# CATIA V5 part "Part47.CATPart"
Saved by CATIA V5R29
Part number: pan head cross recess screw_iso_ISO 7045 - M4 x 6 - Z - 6N
Revision: ANY
Definition: UNKNOWN
Nomenclature: pan head cross recess screw_iso_ISO 7045 - M4 x 6 - Z - 6N
Source: Unknown
Bounding box of the stored display mesh (mm): x 0.079 to 9.1, y -3.991 to 3.991, z -4 to 4
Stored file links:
  C:\Users\Administrator\Desktop\프로젝트\Gripper\Part47.CATPart
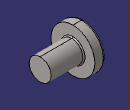
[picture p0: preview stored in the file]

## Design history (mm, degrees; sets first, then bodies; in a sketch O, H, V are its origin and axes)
Body1 "RecessCore" (main body)
  Solid1: solid without history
